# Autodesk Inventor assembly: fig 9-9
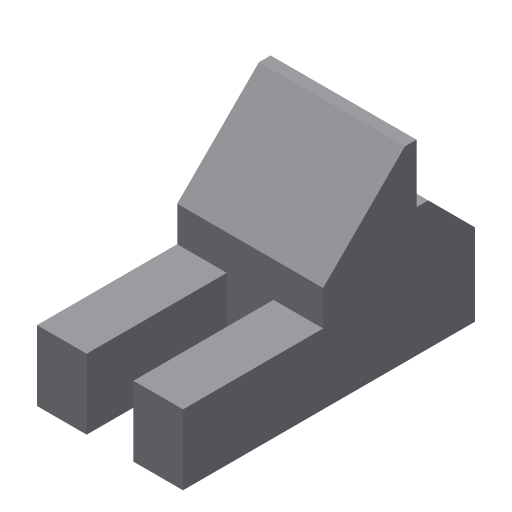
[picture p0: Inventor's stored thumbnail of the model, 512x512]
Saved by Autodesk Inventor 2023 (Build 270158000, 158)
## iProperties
Created: 2002-01
Part Number: fig 9-9
Document SubType Name: Assembly
Designer: ***
Control State: 0
Master: False
Checked Out: False
Shininess: 64.0
Length Units: 11269
Angle Units: 11279
Time Units: 11290
Mass Units: 11283
Length Display Precision: 3
Angle Display Precision: 2
Density: 0.0
Volumn: 0.0
Area: 0.0
PropertySet Name: Model Information
Author: ***
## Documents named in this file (3)
- D:\PROJECTS\Project 2022\Autodesk Inventor For Professional 2023\RESOURCES INVENTOR 2023\RESOURCES INVENTOR 2023\Inventor_2023_Part\Inventor_2023_Part\c09_Inv_2023_prt\fig 9-9.iam
- D:\PROJECTS\Project 2022\Autodesk Inventor For Professional 2023\RESOURCES INVENTOR 2023\RESOURCES INVENTOR 2023\Inventor_2023_Part\Inventor_2023_Part\c09_Inv_2023_prt\Part3.ipt
- D:\PROJECTS\Project 2022\Autodesk Inventor For Professional 2023\RESOURCES INVENTOR 2023\RESOURCES INVENTOR 2023\Inventor_2023_Part\Inventor_2023_Part\c09_Inv_2023_prt\Part4.ipt
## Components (2 placed, 2 different names)
1. Part3:1 — Mate:1
2. Part4:1 — Mate:1
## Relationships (1: Mate 1)
- Mate:1: Part3:1 ↔ Part4:1
